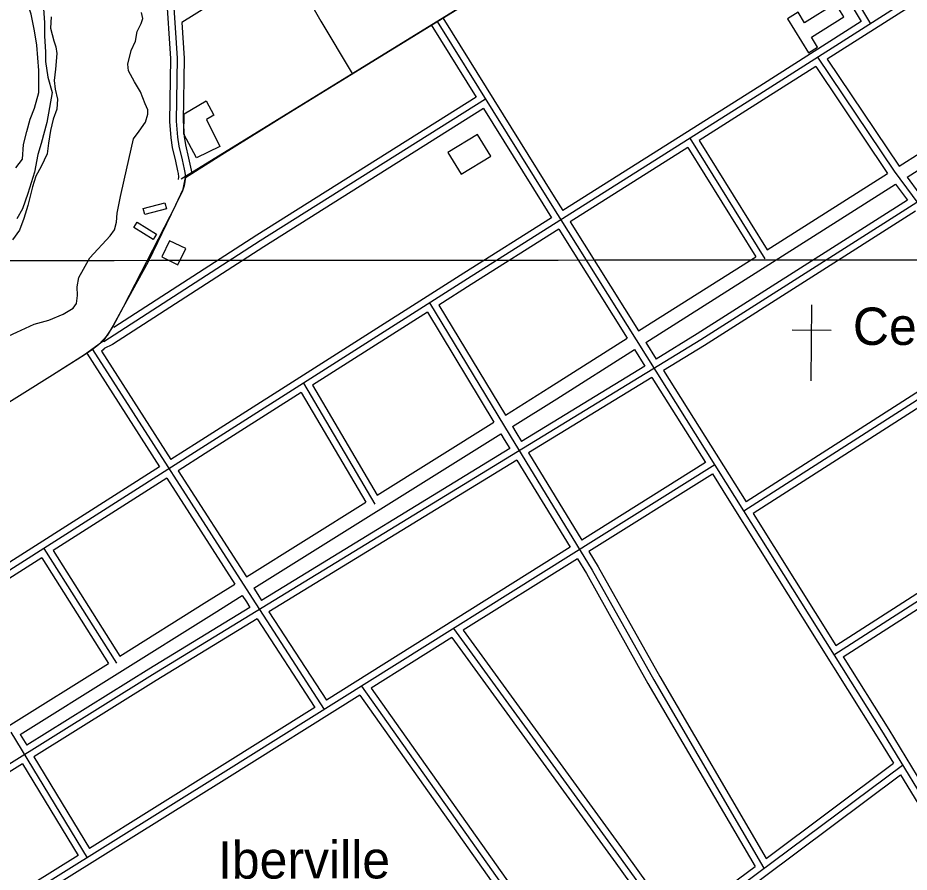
# Model space of a CAD drawing. Extents: x 3297772 to 3335630, y 634068 to 659439.
# Drawn here: x 3308401 to 3310382, y 647184 to 649082 of the extents above; entities that cross this region are included whole.
import ezdxf

# ---------------------------------------------------------------- set-up
doc = ezdxf.new("R2010")
doc.units = 0
for name, color, linetype in [('V-BLDG-IDEN', 7, 'Continuous'), ('V-BLDG-OTLN', 7, 'Continuous'), ('V-GRID-MAJR', 7, 'Continuous'), ('V-ROAD-CNTR', 7, 'Continuous'), ('V-SITE-OTLN', 7, 'Continuous'), ('V-SITE-OTLN-IDEN', 7, 'Continuous'), ('V-SITE-VEGE', 7, 'Continuous'), ('V-TOPO-SHOR', 7, 'Continuous')]:
    doc.layers.add(name, color=color, linetype=linetype)

msp = doc.modelspace()

# ---------------------------------------------------------------- linework, layer by layer
at = {"layer": 'V-BLDG-OTLN'}
for points in [[(3310218.0345265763, 649113.8327456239), (3310149.2906640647, 649070.8638315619), (3310134.761693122, 649094.106785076), (3310110.9797406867, 649079.2408148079), (3310157.84764695, 649004.263964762), (3310178.125606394, 649016.9389394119), (3310164.26763411, 649039.1098950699), (3310236.5144896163, 649084.2678047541)], [(3308849.907262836, 648795.6613819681), (3308798.043366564, 648770.6904319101), (3308770.203422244, 648823.0953271), (3308771.004420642, 648868.3352366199), (3308819.7253232, 648897.329178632), (3308836.941288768, 648865.2942427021), (3308820.363321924, 648856.0202612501)], [(3309422.261118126, 648822.934327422), (3309356.737249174, 648782.922407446), (3309386.3011900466, 648734.508504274), (3309451.825058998, 648774.5204242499)], [(3308731.731499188, 648657.6126580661), (3308683.4175958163, 648644.737683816), (3308679.8126030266, 648658.26565676), (3308728.1255064, 648671.1406310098)], [(3308701.8525589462, 648589.6717939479), (3308659.18064429, 648615.7307418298), (3308666.4766296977, 648627.678717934), (3308709.148544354, 648601.6197700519)], [(3308738.504485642, 648586.643800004), (3308721.114520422, 648550.6218720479), (3308757.13544838, 648533.2309068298), (3308774.526413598, 648569.252834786)]]:
    msp.add_lwpolyline(points, close=True, dxfattribs=at)
at = {"layer": 'V-GRID-MAJR'}
msp.add_spline([(3301875.511, 648538.54), (3307136.054, 648541.983), (3312396.597, 648546.191), (3317657.139, 648551.165), (3322917.681, 648556.903), (3328178.222, 648563.407), (3333438.761, 648570.676), (3333438.762, 648570.676)], degree=3, dxfattribs=at)
at = {"layer": 'V-ROAD-CNTR'}
for points in [[(3312695.4435717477, 651149.2656747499), (3311525.301912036, 650438.1720969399), (3310854.68125328, 650011.558950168), (3309964.594033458, 649463.1000470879), (3308763.833434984, 648723.4155264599)], [(3312939.259084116, 650719.7405338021), (3312147.8886668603, 650226.4545203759), (3311603.3287559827, 649890.6091920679), (3310922.80111704, 649468.348036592), (3310057.579847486, 648917.3251386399), (3309400.102162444, 648502.041969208), (3308809.789343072, 648126.674719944), (3308064.599833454, 647651.8196696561), (3307615.6257314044, 647365.3602425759), (3307608.5777455, 647358.1752569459), (3307605.153752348, 647352.5692681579), (3307604.129754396, 647346.629280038), (3307606.361749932, 647341.7572897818), (3307617.461727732, 647320.5463322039), (3307621.65271935, 647311.931349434), (3307623.69271527, 647303.7813657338), (3307622.4197178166, 647297.7103778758), (3307620.646721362, 647291.379390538), (3307614.8467329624, 647284.846403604), (3307604.638753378, 647278.2334168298), (3306995.5399715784, 646891.920189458)], [(3308752.507457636, 648666.5346402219), (3308768.289426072, 648701.1635709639), (3308774.102414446, 648727.3205186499), (3308854.756253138, 648778.183416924), (3309003.575955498, 648871.1002310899), (3309462.9030368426, 649154.052665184), (3309689.957582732, 649293.920385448), (3309910.267142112, 649429.6341140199), (3310107.8487469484, 649551.3718705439), (3310370.686221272, 649713.3285466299), (3310640.1676823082, 649879.3792145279), (3310865.89123086, 650018.689935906), (3311087.3317879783, 650159.5586541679), (3311313.702335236, 650303.5643661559), (3311454.208054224, 650392.9451873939), (3311582.125798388, 650472.7040278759), (3311736.615489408, 650566.5868401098), (3311915.161132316, 650675.088623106), (3312000.5909614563, 650727.004519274)], [(3313326.0353105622, 650149.436674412), (3312559.07284449, 649661.2426508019), (3312271.130420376, 649481.9440093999), (3311691.5125796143, 649052.7308678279), (3310895.1911722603, 648549.8458736), (3310014.446933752, 647985.7830017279)], [(3312538.3908858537, 648862.342248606), (3312246.516469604, 649205.222562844), (3311949.495063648, 649557.7548577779), (3311933.901094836, 649569.93883341), (3311922.9381167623, 649576.9168194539), (3311909.680143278, 649578.560816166), (3311892.29917804, 649578.365816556), (3311870.545221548, 649576.1998208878), (3311806.407349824, 649556.6208600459), (3311715.9435307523, 649509.5969540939), (3309918.72812519, 648366.885239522), (3308700.572561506, 647622.2597287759), (3307816.6983292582, 647071.6478300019), (3307154.2246542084, 646652.5346682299)], [(3310021.750919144, 649498.22897683), (3310275.069412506, 649073.620826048)], [(3310034.48289368, 649506.1649609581), (3310295.416371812, 649068.7928357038)], [(3308993.4169608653, 649213.4684978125), (3309033.2830000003, 649147.684), (3309074.1890000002, 649074.435), (3309144.3741436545, 648957.8340459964)], [(3308981.1340152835, 649205.8264546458), (3308765.422431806, 649071.6178300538)], [(3310462.1490383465, 649157.1946589), (3310199.2035642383, 648989.7359938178)], [(3308731.0315005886, 649137.6236980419), (3308740.609481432, 648991.5169902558), (3308738.3724859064, 648851.841269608), (3308741.349479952, 648815.122343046), (3308744.386473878, 648793.8683855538), (3308751.4504597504, 648763.2854467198), (3308756.091450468, 648742.1734889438), (3308757.768447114, 648735.8855015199), (3308758.452445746, 648728.3635165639), (3308757.641447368, 648722.8185276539)], [(3308745.9664707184, 649139.1026950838), (3308755.617451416, 648991.8879895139), (3308753.382455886, 648852.3282686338), (3308756.263450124, 648816.7913397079), (3308759.1454443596, 648796.6223800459), (3308766.083430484, 648766.583440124), (3308770.6704213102, 648745.718481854), (3308772.591417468, 648738.5154962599), (3308773.551415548, 648727.95051739), (3308770.6704213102, 648708.261556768), (3308766.6894292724, 648695.609582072), (3308752.657457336, 648666.834639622)], [(3309345.38427188, 649081.6468099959), (3309593.01377662, 648684.4086044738), (3309612.262738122, 648653.7916657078)], [(3308765.422431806, 649071.6178300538), (3308770.6254214, 648992.2589887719), (3308768.3924258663, 648852.81526766), (3308771.177420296, 648818.46033637), (3308773.9044148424, 648799.3763745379), (3308780.7164012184, 648769.8814335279), (3308788.029386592, 648736.6185000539)], [(3309319.825322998, 649065.9388414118), (3309419.761123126, 648905.6241620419)], [(3309332.607297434, 649073.7878257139), (3309580.2998020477, 648676.4496203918), (3309993.824974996, 648018.6889359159), (3310323.404315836, 647492.783987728), (3310571.268820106, 647087.1877989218), (3310807.283348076, 646702.4105684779), (3311025.519911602, 646366.1832409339), (3311127.914706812, 646231.266510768), (3311267.169428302, 646051.4268704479)], [(3310275.0714125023, 649073.6198260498), (3310049.545863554, 648929.9921133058), (3309612.26373812, 648653.79066571)], [(3310376.8012090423, 648728.0905171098), (3310468.8800248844, 648786.3724005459), (3310919.1741242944, 649069.6118340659)], [(3310178.165606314, 648994.1209850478), (3310348.311266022, 648741.4214904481), (3310441.086080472, 648615.774741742), (3310635.325691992, 648316.8963395), (3310951.2520601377, 647814.0453452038), (3311290.506381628, 647296.382380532), (3311523.6179154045, 646932.337108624), (3311656.765649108, 646724.506524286)], [(3310199.2015642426, 648989.73499382), (3310359.036244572, 648752.35046859)], [(3310173.8916148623, 648973.616026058), (3310065.613831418, 648904.6581639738), (3309914.88313288, 648809.4523543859)], [(3310173.889614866, 648973.6140260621), (3310333.67729529, 648736.2985006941)], [(3309440.3940818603, 648900.8801715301), (3308939.993082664, 648586.12580104), (3308592.7257772, 648361.882249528)], [(3309419.762123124, 648905.6231620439), (3308931.9310987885, 648598.7757757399), (3308614.2847340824, 648393.6591859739)], [(3310359.036244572, 648752.35046859), (3310452.8720569, 648811.744349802), (3310614.153734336, 648913.1911469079)], [(3309435.633091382, 648880.1642129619), (3308948.05506654, 648573.47582634), (3308611.337739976, 648356.044261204), (3308593.239776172, 648347.4012784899)], [(3309435.631091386, 648880.1662129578), (3309567.585827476, 648668.4906363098), (3309586.89878885, 648637.7706977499)], [(3309894.2731741, 648814.1753449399), (3310061.039840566, 648546.2618807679)], [(3309914.8821328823, 648809.451354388), (3310065.913830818, 648566.8158396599)], [(3309889.5191836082, 648793.4313864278), (3309628.2307061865, 648628.3937165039)], [(3309889.51818361, 648793.43038643), (3310040.564881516, 648550.7708717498)], [(3310214.2215342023, 647667.0056392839), (3311349.299264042, 648395.2291828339), (3311939.060084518, 648775.247422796)], [(3310065.913830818, 648566.8158396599), (3310333.67729529, 648736.2985006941)], [(3310376.8012090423, 648728.0905171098), (3310403.018156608, 648692.583588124)], [(3309796.480369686, 648360.7712517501), (3310351.386259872, 648712.003549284)], [(3310351.386259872, 648712.003549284), (3310377.640207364, 648676.4476203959)], [(3308752.507457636, 648666.5346402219), (3308635.3006920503, 648439.1980948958), (3308612.3077380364, 648396.4581803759), (3308590.2817820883, 648362.96124737), (3308549.587863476, 648333.5343062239), (3308478.6350053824, 648288.099397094), (3308287.3353879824, 648168.914635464), (3308228.423505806, 648132.680707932), (3308194.0385745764, 648098.154776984), (3308121.64171937, 648024.190924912), (3308017.39692786, 647944.70708388), (3307973.7430151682, 647918.9731353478), (3307781.580399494, 647845.4142824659), (3307689.009584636, 647796.941379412), (3307663.105636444, 647771.3984304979), (3307639.5876834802, 647743.600486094), (3307615.10773244, 647702.121569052), (3307574.2868140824, 647647.3226786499), (3307538.351885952, 647601.8957695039), (3307504.4889536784, 647566.5878401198), (3307302.7243572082, 647424.1521249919), (3307039.646883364, 647219.9345334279), (3306925.0941124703, 647135.765701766)], [(3308752.657457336, 648666.834639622), (3308690.7825810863, 648539.9448934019), (3308635.203692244, 648439.0180952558), (3308613.157736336, 648398.037177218), (3308599.7107632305, 648375.9472213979), (3308580.501801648, 648355.7772617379), (3308566.8568289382, 648345.0882831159), (3308548.3268659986, 648332.7273078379), (3308478.6350053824, 648288.099397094), (3308287.3383879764, 648168.9156354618)], [(3310377.640207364, 648676.4476203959), (3309910.7921410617, 648379.6142140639), (3309819.657323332, 648323.90632548)], [(3310395.504171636, 648652.254668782), (3309926.664109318, 648354.1562649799), (3309835.6252913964, 648298.5063762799)], [(3309586.899788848, 648637.7706977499), (3309392.072178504, 648514.711943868), (3308801.7343591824, 648139.3286946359), (3308741.502479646, 648100.9477713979)], [(3309628.229706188, 648628.3937165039), (3309780.514401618, 648386.169200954)], [(3309602.866756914, 648612.372748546), (3309408.132146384, 648489.3719945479), (3309336.415289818, 648443.769085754)], [(3309602.865756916, 648612.372748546), (3309755.164452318, 648370.1242330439)], [(3309780.514401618, 648386.169200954), (3310040.564881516, 648550.7708717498)], [(3309315.9793306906, 648448.5500761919), (3309494.860972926, 648153.3266666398), (3309677.375607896, 647854.9882633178), (3309814.2893340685, 647610.983751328), (3310059.000844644, 647192.681587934)], [(3309336.415289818, 648443.769085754), (3309484.411993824, 648199.5175742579)], [(3309311.09434046, 648427.6681179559), (3309056.0908504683, 648265.5174422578)], [(3309311.0933404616, 648427.6681179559), (3309458.971044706, 648183.6126060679)], [(3309484.411993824, 648199.5175742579), (3309582.99879665, 648261.1504509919), (3309755.164452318, 648370.1242330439)], [(3310583.9947946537, 648368.35623658), (3310019.1129244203, 648006.5839601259)], [(3308566.903828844, 648345.1192830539), (3308921.7911190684, 647792.3883885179), (3309082.173798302, 647545.4608823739)], [(3308593.239776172, 648347.4012784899), (3308590.6107814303, 648344.6422840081), (3308586.9007888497, 648341.7372898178)], [(3308586.9007888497, 648341.7372898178), (3308741.502479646, 648100.9477713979)], [(3309499.959962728, 648173.857625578), (3309598.972764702, 648235.75650178), (3309771.132420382, 648344.7262838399)], [(3309771.132420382, 648344.7262838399), (3309794.0583745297, 648308.2593567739)], [(3309796.480369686, 648360.7712517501), (3309819.657323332, 648323.90632548)], [(3310600.342761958, 648343.2002868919), (3310035.044892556, 647981.16201097)], [(3308554.30585404, 648336.9782993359), (3308716.2025302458, 648084.825803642)], [(3309794.059374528, 648308.2593567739), (3309520.1089224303, 648140.8006916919)], [(3309810.0273425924, 648282.8594075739), (3309535.7648911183, 648115.2097428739)], [(3309810.026342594, 648282.8594075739), (3309928.8001050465, 648093.9367854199)], [(3309835.6252913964, 648298.5073762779), (3310006.529949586, 648026.663919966), (3310019.1129244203, 648006.584960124)], [(3309035.7998910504, 648270.3904325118), (3309194.5735735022, 648001.262970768)], [(3309056.0908504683, 648265.5174422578), (3309199.9445627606, 648021.6789299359)], [(3309030.761901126, 648249.4104744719), (3308817.8443269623, 648114.0207452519), (3308757.711447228, 648075.702821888)], [(3309030.760901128, 648249.4114744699), (3309174.4986136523, 648005.7709617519)], [(3309199.9445627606, 648021.6789299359), (3309458.971044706, 648183.6126060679)], [(3309499.959962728, 648173.857625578), (3309507.672947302, 648161.127651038), (3309520.1089224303, 648140.8006916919)], [(3308925.34011197, 647814.623344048), (3309474.520013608, 648157.9526573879)], [(3309474.520013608, 648157.9526573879), (3309482.0489985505, 648145.5256822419), (3309494.511973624, 648125.153722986)], [(3309494.5129736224, 648125.1547229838), (3308942.648077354, 647787.814397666)], [(3309535.76389112, 648115.2097428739), (3309654.125654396, 647921.736129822)], [(3309949.4930636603, 648089.2037948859), (3308857.6572473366, 647404.7061638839), (3307354.8132530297, 646467.636038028)], [(3308716.2025302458, 648084.825803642), (3308056.534849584, 647664.4676443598), (3307775.913410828, 647485.422002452)], [(3309510.167942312, 648099.562774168), (3308958.9950446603, 647762.6464480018)], [(3309510.167942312, 648099.562774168), (3309628.705705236, 647905.8001616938)], [(3309928.8011050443, 648093.9357854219), (3309654.1266543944, 647921.7351298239)], [(3308757.711447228, 648075.702821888), (3308909.1301443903, 647839.871293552)], [(3309944.7680731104, 648068.5378362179), (3309669.7826230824, 647896.14218101)], [(3309944.767073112, 648068.538836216), (3309981.120000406, 648010.7139518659), (3310310.6493413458, 647484.890003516), (3310346.641269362, 647425.9941213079)], [(3308732.4124978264, 648059.5798541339), (3308479.995002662, 647898.7341758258)], [(3308732.4124978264, 648059.5798541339), (3308883.689195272, 647823.9673253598)], [(3310218.8805248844, 647687.8165976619), (3310784.753393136, 648050.8588715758)], [(3310234.81249302, 647662.394648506), (3310800.714361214, 648025.4559223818)], [(3308909.1301443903, 647839.871293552), (3309174.4986136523, 648005.7709617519)], [(3310035.043892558, 647981.163010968), (3310218.8815248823, 647687.8165976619)], [(3308459.3440439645, 647903.3611665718), (3308620.2227222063, 647648.236676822)], [(3308479.995002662, 647898.7341758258), (3308628.0987064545, 647663.8676455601)], [(3309628.7077052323, 647905.8001616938), (3309086.712789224, 647566.010841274)], [(3309669.781623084, 647896.144181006), (3309690.3185820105, 647862.5752481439), (3309827.3043080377, 647618.4417364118), (3310063.47783569, 647214.7355438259)], [(3308454.69605326, 647882.613208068), (3308223.964514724, 647735.584502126)], [(3308454.6950532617, 647882.6122080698), (3308602.679757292, 647647.935677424)], [(3309644.3636739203, 647880.2072128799), (3309390.9131808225, 647721.313530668)], [(3309644.362673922, 647880.208212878), (3309664.4326337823, 647847.401278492), (3309801.274360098, 647603.5257662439), (3310039.281884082, 647196.6845799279)], [(3308628.0987064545, 647663.8676455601), (3308821.359319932, 647785.0004032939), (3308883.689195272, 647823.9673253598)], [(3308925.34011197, 647814.623344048), (3308934.3920938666, 647800.525372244), (3308942.648077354, 647787.8153976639)], [(3308406.807149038, 647489.758993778), (3308837.277288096, 647759.570454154), (3308899.9001628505, 647798.720375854)], [(3308899.9001628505, 647798.720375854), (3308909.19014427, 647784.2514047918), (3308917.0421285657, 647772.1624289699)], [(3308917.0421285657, 647772.1624289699), (3308692.69557726, 647635.0247032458), (3308421.28612008, 647465.950041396)], [(3308958.9950446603, 647762.6474479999), (3309086.712789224, 647566.010841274)], [(3308933.389095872, 647746.9934793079), (3308708.4495457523, 647609.4947543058), (3308436.8730889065, 647440.315092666)], [(3308933.389095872, 647746.994479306), (3309061.291840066, 647550.073873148)], [(3309369.33422398, 647725.4885223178), (3309741.9064788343, 647212.9445474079), (3309862.195238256, 647045.7218818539)], [(3309390.9131808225, 647721.313530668), (3309754.0614545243, 647221.7345298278), (3309865.452231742, 647066.8818395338)], [(3309365.436231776, 647705.340562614), (3309186.528589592, 647593.178786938)], [(3309365.4352317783, 647705.340562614), (3309729.7515031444, 647204.1545649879), (3309841.4162798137, 647048.9208754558)], [(3310234.81249302, 647662.395648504), (3310336.1592903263, 647500.6779719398), (3310449.97706269, 647314.430344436)], [(3308379.743203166, 647508.201956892), (3308602.679757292, 647647.935677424)], [(3309165.1246324, 647597.4647783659), (3309661.45363974, 646895.7171818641)], [(3309186.528589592, 647593.1797869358), (3309664.80863303, 646916.9501393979)], [(3309161.071640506, 647577.219818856), (3308865.609231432, 647391.987189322), (3308371.8252190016, 647084.0978051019)], [(3309161.070640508, 647577.219818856), (3309640.7686811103, 646898.9861753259)], [(3309061.292840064, 647550.073873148), (3308849.70526324, 647417.4251384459), (3308560.461841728, 647237.0724991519)], [(3308385.83619098, 647495.3759825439), (3308555.5258516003, 647216.3175406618)], [(3308406.807149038, 647489.758993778), (3308421.285120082, 647465.950041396)], [(3308436.8730889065, 647440.316092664), (3308560.4608417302, 647237.0724991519)], [(3308411.4091398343, 647424.452124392), (3307824.674313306, 647058.9438554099), (3307797.7903670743, 647041.935889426)], [(3308001.858958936, 645644.740683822), (3308818.024326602, 646264.3884445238), (3309463.4090358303, 646747.727477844), (3309971.6300193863, 647127.4977183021), (3310366.5712295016, 647422.1471290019)], [(3308411.407139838, 647424.4531243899), (3308535.002892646, 647221.1985309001)], [(3310063.47783569, 647214.7355438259), (3310346.641269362, 647425.99312131)], [(3308380.0142026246, 645913.0101472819), (3308827.0553085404, 646252.4114684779), (3309472.3940178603, 646735.7165018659), (3309980.6040014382, 647115.4787423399), (3310362.35223794, 647400.2841727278)], [(3310362.351237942, 647400.286172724), (3310531.1759002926, 647124.02872524)], [(3308535.003892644, 647221.1985309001), (3307921.6901192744, 646838.778295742)], [(3309865.4512317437, 647066.880839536), (3309962.656037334, 647139.5166942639), (3310039.281884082, 647196.6845799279)]]:
    msp.add_lwpolyline(points, dxfattribs=at)
at = {"layer": 'V-SITE-OTLN'}
for p, q in [((3310164.023580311, 648275.2739637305), (3310165.432580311, 648443.9599637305)), ((3310208.534580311, 648387.3729637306), (3310121.3745803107, 648388.1009637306))]:
    msp.add_line(p, q, dxfattribs=at)
at = {"layer": 'V-SITE-VEGE'}
for points in [[(3308396.664, 649269.5480000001), (3308401.577, 649230.22), (3308426.139, 649173.687), (3308438.421, 649146.65), (3308450.7, 649122.0700000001), (3308458.0670000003, 649102.405), (3308460.5270000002, 649070.452), (3308460.5270000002, 649040.954), (3308462.982, 649006.544), (3308462.982, 648984.421), (3308467.895, 648950.009), (3308477.722, 648915.596), (3308465.44, 648849.231), (3308453.1580000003, 648802.528), (3308445.789, 648777.948), (3308438.421, 648738.621), (3308423.681, 648691.92), (3308411.401, 648657.507), (3308399.119, 648635.387)], [(3308396.664, 648748.455), (3308411.401, 648768.118), (3308413.859, 648800.071), (3308421.2260000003, 648829.568), (3308428.594, 648856.606), (3308438.421, 648881.186), (3308448.245, 648915.596), (3308448.245, 648964.759), (3308443.3340000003, 649021.292), (3308438.421, 649053.245), (3308431.0500000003, 649090.115), (3308408.946, 649156.48), (3308377.0130000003, 649215.475)]]:
    msp.add_lwpolyline(points, dxfattribs=at)
at = {"layer": 'V-TOPO-SHOR'}
for points in [[(3308379.864, 648375.004), (3308437.894, 648401.522), (3308469.911, 648410.011), (3308501.954, 648423.687), (3308524.484, 648436.545), (3308531.447, 648446.883), (3308534.126, 648465.018), (3308533.3510000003, 648484.036), (3308536.907, 648504.759), (3308561.315, 648548.7220000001), (3308606.488, 648597.767), (3308616.056, 648610.686), (3308620.4590000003, 648627.951), (3308622.282, 648647.8200000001), (3308629.372, 648684.949), (3308637.3200000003, 648721.208), (3308658.497, 648812.7170000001), (3308670.678, 648829.947), (3308684.6, 648849.757), (3308689.872, 648867.88), (3308689.917, 648877.389), (3308683.929, 648890.379), (3308673.685, 648917.22), (3308660.827, 648939.75), (3308647.116, 648964.015), (3308645.457, 648978.716), (3308653.379, 649008.926), (3308662.984, 649029.623), (3308666.541, 649051.211), (3308675.272, 649069.319), (3308678.782, 649080.5380000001), (3308676.249, 649093.512)], [(3308475.7, 649084.094), (3308473.853, 649059.0380000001), (3308481.4960000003, 649030.483), (3308485.756, 649017.4990000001), (3308488.2770000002, 649002.794), (3308484.654, 648967.378), (3308481.943, 648942.329), (3308484.443, 648923.303), (3308489.522, 648900.808), (3308487.691, 648879.212), (3308479.809, 648856.778), (3308473.64, 648831.743), (3308469.184, 648803.245), (3308466.48, 648779.925), (3308453.381, 648751.466), (3308441.179, 648729.917), (3308434.1550000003, 648706.616), (3308423.589, 648665.183), (3308414.805, 648635.84), (3308405.177, 648609.959), (3308389.518, 648588.426)]]:
    msp.add_lwpolyline(points, dxfattribs=at)

# ---------------------------------------------------------------- texts
at = {"layer": 'V-BLDG-IDEN'}
msp.add_text('Iberville', height=82.99983200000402, rotation=0.0733610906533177, dxfattribs=at).set_placement((3308845.934270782, 647169.7986336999))
at = {"layer": 'V-SITE-OTLN-IDEN'}
msp.add_text('Cem.', height=82.99983200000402, dxfattribs=at).set_placement((3310256.5119797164, 648355.2452628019))

doc.saveas('drawing.dxf')
